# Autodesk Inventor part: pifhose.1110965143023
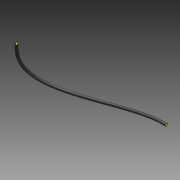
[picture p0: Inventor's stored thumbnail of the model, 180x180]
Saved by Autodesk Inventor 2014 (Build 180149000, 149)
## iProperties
TPVersion: 11.0.2
Company: Autodesk, Inc.
Created: 2005-03
Material: Rubber
Description: Hose
Document SubType Name: Modeling
Designer: Autodesk, Inc.
Stock Number: Parker Hydraulic Hose - No Skive 1/2
Categories: <pipe>
Density: 1 g/cm^3
Appearance: Rubber - Black - Version 1.1
PL: 45.614 in
RPL: 45.625 in
OPL: 43.094 in
ROPL: 43.125 in
Author: Autodesk, Inc.
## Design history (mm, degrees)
sketch "3D Sketch3" dims "d6" = 10, "d7" = 10
workpoint "Work Point7"
workpoint "Work Point8"
workplane "Work Plane3"
sketch "Sketch3"
  geometry: C1 r 11.176 at (0, 0); C2 r 6.35 at (0, 0); 1 further point
  constraints: 2 centre point
workpoint "Work Point9"
sweep "Sweep3" dims "d8" = 0
body "Solid1"
other parameters: "PL" = 1158.5956 [user parameter], "RPL" = 1158.875 [user parameter], "OPL" = 1094.5876 [user parameter], "ROPL" = 1095.375 [user parameter]
